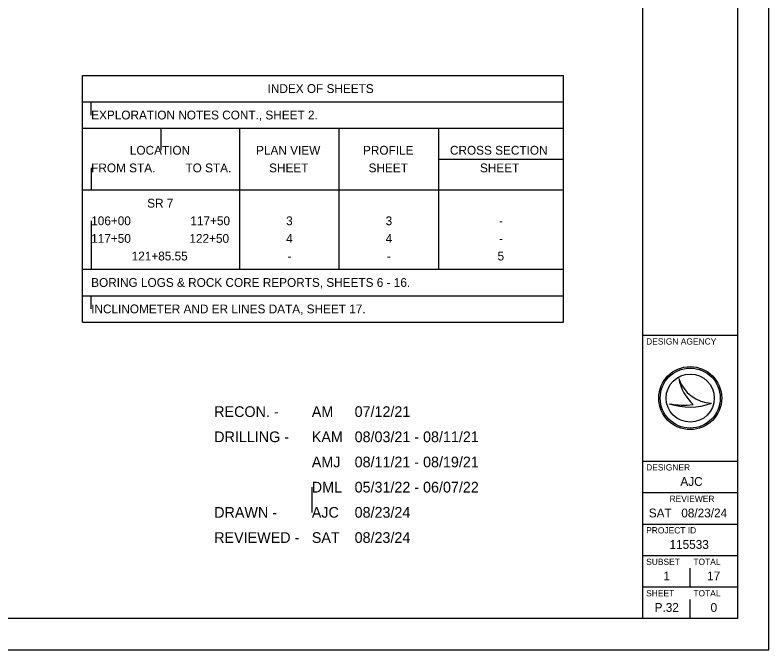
# Model space of a CAD drawing. Extents: x 0 to 34, y 0 to 22.
# Drawn here: x 22.03 to 34, y 0 to 10.08 of the extents above; entities that cross this region are included whole.
import ezdxf

# ---------------------------------------------------------------- set-up
doc = ezdxf.new("R2010")
doc.units = 0
for name, color, linetype in [('SC_Scratch1', 7, 'Continuous'), ('SH_Border', 7, 'Continuous'), ('SH_Cut_Line', 7, 'Continuous'), ('SH_Data', 7, 'Continuous'), ('SH_Text', 7, 'Continuous')]:
    doc.layers.add(name, color=color, linetype=linetype)

msp = doc.modelspace()

# ---------------------------------------------------------------- linework, layer by layer
at = {"layer": 'SC_Scratch1'}
for p, q in [((23.236, 8.496), (23.236, 8.706)), ((24.346, 7.936), (24.346, 8.286)), ((28.757, 7.796), (28.957, 7.796)), ((28.957, 7.796), (30.537, 7.796)), ((30.537, 7.796), (30.737, 7.796)), ((23.236, 7.656), (23.236, 7.306)), ((23.236, 6.816), (23.236, 6.536)), ((23.236, 6.536), (23.236, 6.256)), ((23.236, 6.256), (23.236, 6.046)), ((23.236, 5.416), (23.236, 5.626)), ((26.74, 2.585), (26.74, 2.185))]:
    msp.add_line(p, q, dxfattribs=at)
at = {"layer": 'SH_Border'}
for p, q in [((32, 0.5), (32, 21.5)), ((32, 5), (33.5, 5)), ((32, 3), (33.5, 3)), ((32, 2.5), (33.5, 2.5)), ((32, 2), (33.5, 2)), ((32, 1.5), (33.5, 1.5)), ((32, 1), (33.5, 1))]:
    msp.add_line(p, q, dxfattribs=at)
msp.add_lwpolyline([(1.5, 21.5), (33.5, 21.5), (33.5, 0.5), (1.5, 0.5)], close=True, dxfattribs=at)
at = {"layer": 'SH_Cut_Line'}
msp.add_lwpolyline([(0, 0), (34, 0), (34, 22), (0, 22)], close=True, dxfattribs=at)
at = {"layer": 'SH_Data'}
for p, q in [((23.096, 9.126), (30.737, 9.126)), ((23.096, 5.206), (23.096, 9.126)), ((30.737, 5.206), (30.737, 9.126)), ((23.096, 8.706), (30.737, 8.706)), ((23.096, 8.286), (30.737, 8.286)), ((25.596, 6.046), (25.596, 8.286)), ((27.176, 6.046), (27.176, 8.286)), ((28.757, 6.046), (28.757, 8.286)), ((23.096, 7.306), (30.737, 7.306)), ((23.096, 6.046), (30.737, 6.046)), ((23.096, 5.626), (30.737, 5.626)), ((23.096, 5.206), (30.737, 5.206)), ((32.567, 4.31), (32.567, 4.31)), ((32.75, 4), (32.75, 4)), ((32.417, 3.91), (32.417, 3.91)), ((33.087, 3.919), (33.087, 3.919)), ((32.75, 1), (32.75, 1.3)), ((32.75, 0.5), (32.75, 0.8)), ((32.375, 0.675), (32.375, 0.675))]:
    msp.add_line(p, q, dxfattribs=at)
for radius in [0.5, 0.477, 0.477, 0.382]:
    msp.add_circle((32.75, 4), radius, dxfattribs=at)
for centre, radius, start, end in [((33.116, 4.498), 0.58, 198.9257, 198.9319), ((33.347, 4.47), 0.796, 191.6379, 191.6421), ((33.116, 4.498), 0.58, 198.9319, 267.1657), ((33.347, 4.47), 0.796, 191.6421, 226.0947), ((32.739, 4.87), 1.013, 251.4576, 290.0832), ((32.648, 5.154), 1.266, 259.4964, 259.4995), ((32.739, 4.87), 1.013, 251.4527, 251.4576), ((32.648, 5.154), 1.266, 259.4995, 276.6672)]:
    msp.add_arc(centre, radius, start, end, dxfattribs=at)

# ---------------------------------------------------------------- texts
for s, height, p in [('DESIGN AGENCY', 0.1, (32.05, 4.85)), ('DESIGNER', 0.1, (32.05, 2.85)), ('AJC', 0.14, (32.594, 2.605)), ('REVIEWER', 0.1, (32.422, 2.35)), ('SAT', 0.14, (32.092, 2.105)), ('08/23/24', 0.14, (32.608, 2.105)), ('PROJECT ID', 0.1, (32.05, 1.85)), ('SUBSET', 0.1, (32.05, 1.35)), ('TOTAL', 0.1, (32.8, 1.35)), ('1', 0.14, (32.325, 1.105)), ('17', 0.14, (33.018, 1.105)), ('SHEET', 0.1, (32.05, 0.85)), ('TOTAL', 0.1, (32.8, 0.85)), ('P.32', 0.14, (32.185, 0.605)), ('0', 0.14, (33.073, 0.605))]:
    msp.add_text(s, height=height, dxfattribs=at).set_placement(p)
at = {"layer": 'SH_Text'}
for s, height, p in [('INDEX OF SHEETS', 0.14, (26.038, 8.846)), ('EXPLORATION NOTES CONT., SHEET 2.', 0.14, (23.236, 8.426)), ('LOCATION', 0.14, (23.85, 7.866)), ('PLAN VIEW', 0.14, (25.855, 7.866)), ('PROFILE', 0.14, (27.553, 7.866)), ('CROSS SECTION', 0.14, (28.934, 7.866)), ('FROM STA.', 0.14, (23.236, 7.586)), ('TO STA.', 0.14, (24.733, 7.586)), ('SHEET', 0.14, (26.062, 7.586)), ('SHEET', 0.14, (27.642, 7.586)), ('SHEET', 0.14, (29.411, 7.586)), ('SR 7', 0.14, (24.125, 7.026)), ('106+00', 0.14, (23.236, 6.746)), ('117+50', 0.14, (24.811, 6.746)), ('3', 0.14, (26.332, 6.746)), ('3', 0.14, (27.912, 6.746)), ('-', 0.14, (29.714, 6.746)), ('117+50', 0.14, (23.236, 6.466)), ('122+50', 0.14, (24.796, 6.466)), ('4', 0.14, (26.332, 6.466)), ('4', 0.14, (27.913, 6.466)), ('-', 0.14, (29.714, 6.466)), ('121+85.55', 0.14, (23.879, 6.186)), ('-', 0.14, (26.353, 6.186)), ('-', 0.14, (27.933, 6.186)), ('5', 0.14, (29.69, 6.186)), ('BORING LOGS & ROCK CORE REPORTS, SHEETS 6 - 16.', 0.14, (23.236, 5.766)), ('INCLINOMETER AND ER LINES DATA, SHEET 17.', 0.14, (23.236, 5.346)), ('RECON. -', 0.17, (25.19, 3.7)), ('AM', 0.17, (26.74, 3.7)), ('07/12/21', 0.17, (27.42, 3.7)), ('DRILLING -', 0.17, (25.19, 3.3)), ('08/03/21 - 08/11/21', 0.17, (27.42, 3.3)), ('KAM', 0.17, (26.74, 3.3)), ('AMJ', 0.17, (26.74, 2.9)), ('08/11/21 - 08/19/21', 0.17, (27.42, 2.9)), ('DML', 0.17, (26.74, 2.5)), ('05/31/22 - 06/07/22', 0.17, (27.42, 2.5)), ('08/23/24', 0.17, (27.42, 2.1)), ('DRAWN -', 0.17, (25.19, 2.1)), ('AJC', 0.17, (26.74, 2.1)), ('REVIEWED -', 0.17, (25.19, 1.7)), ('SAT', 0.17, (26.74, 1.7)), ('08/23/24', 0.17, (27.42, 1.7)), ('115533', 0.14, (32.421, 1.605))]:
    msp.add_text(s, height=height, dxfattribs=at).set_placement(p)

doc.saveas('drawing.dxf')
